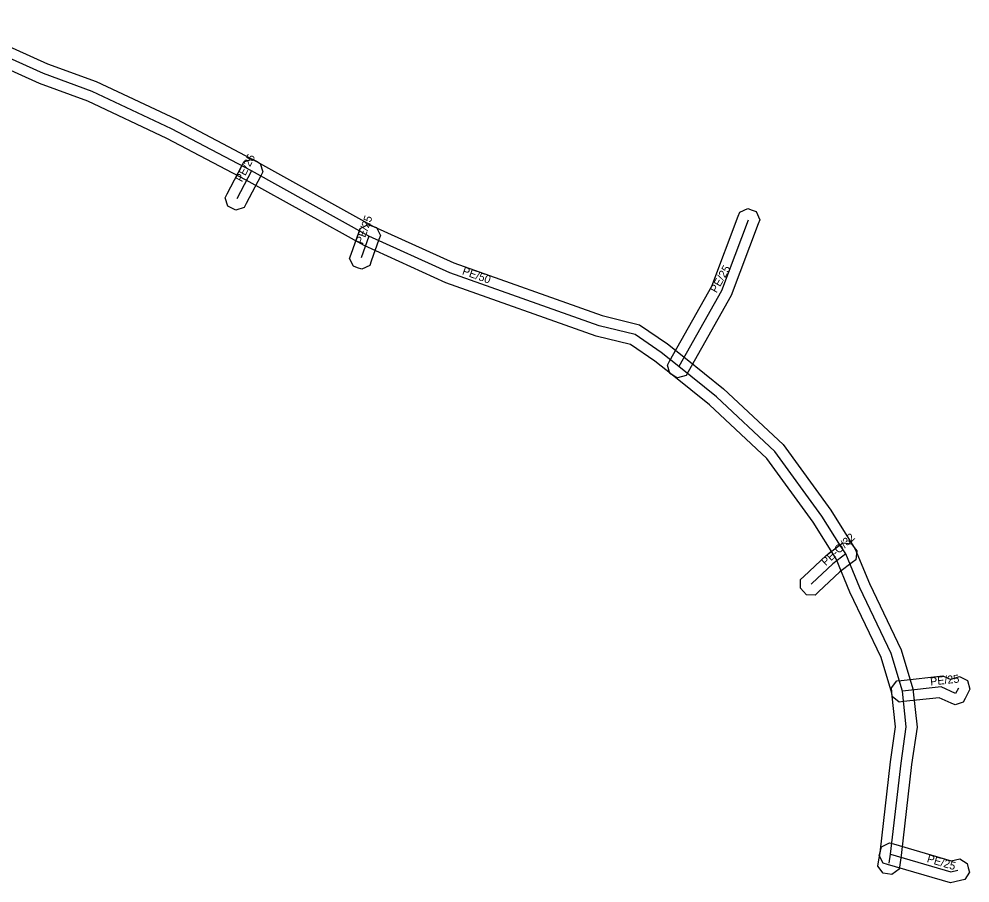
# Model space of a CAD drawing. Extents: x -681050 to -680828, y -1057939 to -1057551.
# Drawn here: x -680916.7 to -680827.6, y -1057899.5 to -1057818.6 of the extents above; entities that cross this region are included whole.
import ezdxf

# ---------------------------------------------------------------- set-up
doc = ezdxf.new("R2010")
doc.units = 0
for name, color, linetype in [('1', 7, 'Continuous'), ('24', 7, 'Continuous'), ('30', 7, 'Continuous')]:
    doc.layers.add(name, color=color, linetype=linetype)

msp = doc.modelspace()

# ---------------------------------------------------------------- linework, layer by layer
at = {"layer": '1'}
msp.add_lwpolyline([(-680923.266, -1057818.585), (-680913.992, -1057822.773), (-680909.435, -1057824.436), (-680901.914, -1057827.975), (-680894.414, -1057831.92), (-680883.44, -1057838.026), (-680875.935, -1057841.432), (-680862.034, -1057846.37), (-680858.538, -1057847.221), (-680855.896, -1057849.015), (-680854.214, -1057850.36), (-680850.654, -1057853.224), (-680845.087, -1057858.435), (-680840.622, -1057864.589), (-680838.318, -1057868.239), (-680836.986, -1057871.474), (-680834.025, -1057877.678), (-680832.916, -1057881.34), (-680832.532, -1057884.929), (-680833.038, -1057888.419), (-680834.019, -1057896.963), (-680834.151, -1057897.831), (-680834.214, -1057898.241), (-680834.882, -1057898.732), (-680835.291, -1057898.669), (-680835.701, -1057898.606), (-680836.192, -1057897.938), (-680836.129, -1057897.529), (-680836.001, -1057896.697), (-680835.022, -1057888.161), (-680834.548, -1057884.891), (-680834.884, -1057881.74), (-680835.895, -1057878.402), (-680838.814, -1057872.286), (-680840.102, -1057869.161), (-680842.278, -1057865.711), (-680846.593, -1057859.765), (-680851.966, -1057854.736), (-680855.466, -1057851.92), (-680857.084, -1057850.625), (-680859.362, -1057849.079), (-680862.606, -1057848.29), (-680876.685, -1057843.288), (-680884.34, -1057839.814), (-680895.366, -1057833.68), (-680902.806, -1057829.765), (-680910.205, -1057826.284), (-680914.748, -1057824.627), (-680924.074, -1057820.415)], dxfattribs=at)
for points in [[(-680893.812, -1057832.896), (-680894.004, -1057833.263), (-680895.374, -1057835.883), (-680895.566, -1057836.25), (-680896.356, -1057836.498), (-680896.723, -1057836.306), (-680897.09, -1057836.114), (-680897.338, -1057835.324), (-680897.146, -1057834.957), (-680895.776, -1057832.337), (-680895.584, -1057831.97), (-680894.794, -1057831.722), (-680894.427, -1057831.914), (-680894.06, -1057832.106)], [(-680847.258, -1057837.388), (-680847.405, -1057837.775), (-680849.952, -1057844.475), (-680853.968, -1057851.63), (-680854.171, -1057851.991), (-680854.968, -1057852.215), (-680855.33, -1057852.012), (-680855.691, -1057851.809), (-680855.915, -1057851.012), (-680855.712, -1057850.65), (-680851.768, -1057843.625), (-680849.275, -1057837.065), (-680849.128, -1057836.678), (-680848.372, -1057836.338), (-680847.985, -1057836.485), (-680847.598, -1057836.632)], [(-680882.809, -1057838.864), (-680882.948, -1057839.254), (-680883.668, -1057841.284), (-680883.806, -1057841.675), (-680884.554, -1057842.031), (-680884.944, -1057841.892), (-680885.335, -1057841.754), (-680885.691, -1057841.006), (-680885.552, -1057840.616), (-680884.832, -1057838.586), (-680884.694, -1057838.195), (-680883.946, -1057837.839), (-680883.556, -1057837.978), (-680883.165, -1057838.116)], [(-680838.273, -1057869.242), (-680838.602, -1057869.494), (-680839.762, -1057870.383), (-680841.763, -1057872.263), (-680842.065, -1057872.547), (-680842.893, -1057872.521), (-680843.177, -1057872.219), (-680843.461, -1057871.917), (-680843.435, -1057871.089), (-680843.133, -1057870.805), (-680841.058, -1057868.857), (-680839.818, -1057867.906), (-680839.49, -1057867.654), (-680838.668, -1057867.763), (-680838.416, -1057868.092), (-680838.164, -1057868.42)], [(-680830.115, -1057880.126), (-680829.363, -1057880.469), (-680829.34, -1057880.426), (-680828.548, -1057880.182), (-680828.182, -1057880.376), (-680827.816, -1057880.57), (-680827.572, -1057881.362), (-680827.766, -1057881.728), (-680828.036, -1057882.238), (-680828.222, -1057882.589), (-680828.974, -1057882.845), (-680829.335, -1057882.68), (-680830.445, -1057882.174), (-680833.793, -1057882.534), (-680834.205, -1057882.578), (-680834.85, -1057882.059), (-680834.894, -1057881.647), (-680834.938, -1057881.235), (-680834.419, -1057880.59), (-680834.007, -1057880.546)], [(-680835.125, -1057895.754), (-680834.728, -1057895.871), (-680829.343, -1057897.455), (-680828.932, -1057897.357), (-680828.529, -1057897.261), (-680827.824, -1057897.695), (-680827.727, -1057898.098), (-680827.631, -1057898.501), (-680828.065, -1057899.206), (-680828.468, -1057899.303), (-680829.397, -1057899.525), (-680835.292, -1057897.789), (-680835.69, -1057897.672), (-680836.086, -1057896.945), (-680835.969, -1057896.548), (-680835.852, -1057896.15)]]:
    msp.add_lwpolyline(points, close=True, dxfattribs=at)
at = {"layer": '24'}
for points in [[(-680835.14, -1057897.68), (-680835.01, -1057896.83), (-680834.03, -1057888.29), (-680833.54, -1057884.91), (-680833.9, -1057881.54), (-680834.96, -1057878.04), (-680837.9, -1057871.88), (-680839.21, -1057868.7), (-680839.687, -1057867.943), (-680841.45, -1057865.15), (-680845.84, -1057859.1), (-680851.31, -1057853.98), (-680854.84, -1057851.14), (-680856.49, -1057849.82), (-680858.95, -1057848.15), (-680862.32, -1057847.33), (-680876.31, -1057842.36), (-680883.89, -1057838.92), (-680894.89, -1057832.8), (-680902.36, -1057828.87), (-680909.82, -1057825.36), (-680914.37, -1057823.7), (-680923.67, -1057819.5)], [(-680894.89, -1057832.8), (-680896.26, -1057835.42)], [(-680848.34, -1057837.42), (-680850.86, -1057844.05), (-680854.84, -1057851.14)], [(-680883.89, -1057838.92), (-680884.61, -1057840.95)], [(-680839.21, -1057868.7), (-680840.41, -1057869.62), (-680842.38, -1057871.47), (-680842.448, -1057871.534)], [(-680828.65, -1057881.26), (-680828.92, -1057881.77), (-680830.28, -1057881.15), (-680833.9, -1057881.54)], [(-680835.01, -1057896.83), (-680829.37, -1057898.49), (-680828.7, -1057898.33)]]:
    msp.add_lwpolyline(points, dxfattribs=at)

# ---------------------------------------------------------------- texts
at = {"layer": '30'}
for s, rotation, p in [('PE/25', 62.3949, (-680895.775, -1057833.91)), ('PE/25', 70.47143, (-680884.45, -1057839.735)), ('PE/50', 340.44223, (-680875.2, -1057842.483)), ('PE/25', 60.69215, (-680851.314, -1057844.303)), ('PE-O/32', 43.20072, (-680841.078, -1057869.859)), ('PE/25', 6.14903, (-680831.26, -1057881.034)), ('PE/25', 343.59946, (-680831.66, -1057897.557))]:
    msp.add_text(s, height=0.75, rotation=rotation, dxfattribs=at).set_placement(p)

doc.saveas('drawing.dxf')
